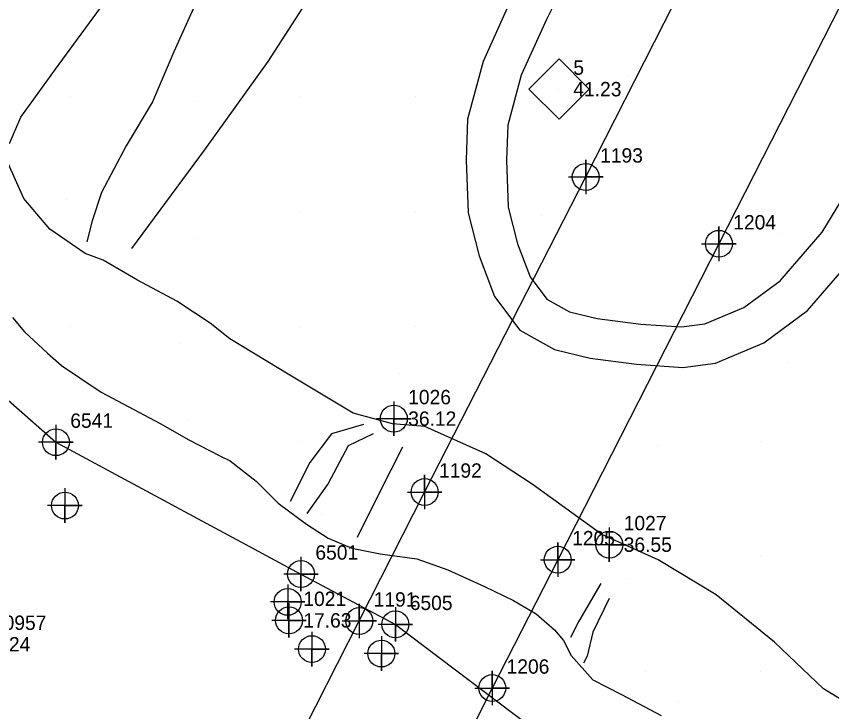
# Model space of a CAD drawing. Extents: x 2062781 to 2066835, y 358981 to 366501.
# Drawn here: x 2064361.2 to 2064503, y 362163.3 to 362284.3 of the extents above; entities that cross this region are included whole.
import ezdxf

# ---------------------------------------------------------------- set-up
doc = ezdxf.new("R2010")
doc.units = 0
for name, color, linetype in [('COGO Default Point Elevation', 7, 'Continuous'), ('COGO Default Point Number', 7, 'Continuous'), ('CTL Supplemental Horizontal and Vertical CELL', 7, 'Continuous'), ('CTL Supplemental Horizontal and Vertical Cogo Elevation', 7, 'Continuous'), ('CTL Supplemental Horizontal and Vertical Cogo Number', 7, 'Continuous'), ('Exist DTM Breakline Underwater', 7, 'Continuous'), ('Exist DTM Breakline Underwater Cogo Elevation', 7, 'Continuous'), ('Exist DTM Breakline Underwater Cogo Number', 7, 'Continuous'), ('Exist DTM Breakline Underwater Cogo Point CELL', 7, 'Continuous'), ('Exist DTM Regular Point CELL', 7, 'Continuous'), ('Exist DTM Regular Point Underwater CELL', 7, 'Continuous'), ('Exist DTM Ridgeline Cogo Elevation', 7, 'Continuous'), ('Exist DTM Ridgeline Cogo Number', 7, 'Continuous'), ('Exist Structure Major Deck Tunnel Box Culvert', 7, 'Continuous'), ('Exist Structure Major Deck Tunnel Box Culvert Cogo Number', 7, 'Continuous'), ('Exist Structure Major Deck Tunnel Box Culvert Cogo Point CELL', 7, 'Continuous'), ('PH Exist DTM Breakline', 7, 'Continuous'), ('PH Exist DTM Point', 7, 'Continuous')]:
    doc.layers.add(name, color=color, linetype=linetype)

msp = doc.modelspace()

# ---------------------------------------------------------------- linework, layer by layer
at = {"layer": 'CTL Supplemental Horizontal and Vertical CELL'}
msp.add_line((2064455.54, 362271.6), (2064455.54, 362271.6), dxfattribs=at)
msp.add_lwpolyline([(2064450.33, 362271.61), (2064455.57, 362276.86), (2064460.82, 362271.61), (2064455.58, 362266.36)], close=True, dxfattribs=at)
at = {"layer": 'Exist DTM Breakline Underwater'}
msp.add_line((2064368.08, 362210.17), (2064410.69, 362187.23), dxfattribs=at)
for points in [[(2064339.75, 362248.83), (2064351.39, 362224.83), (2064368.08, 362210.17)], [(2064410.69, 362187.23), (2064427.1, 362178.47), (2064455.36, 362157.12), (2064487.72, 362143.73), (2064527.72, 362110.81), (2064562.48, 362081.09), (2064591.81, 362074.54), (2064612.39, 362060.79)]]:
    msp.add_lwpolyline(points, dxfattribs=at)
at = {"layer": 'Exist DTM Breakline Underwater Cogo Point CELL'}
for points in [[(2064368.08, 362213.17), (2064368.08, 362207.17), (2064368.08, 362210.17), (2064371.08, 362210.17), (2064365.08, 362210.17)], [(2064368.08, 362213.17), (2064368.08, 362207.17), (2064368.08, 362210.17), (2064371.08, 362210.17), (2064365.08, 362210.17)], [(2064368.08, 362213.17), (2064368.08, 362207.17), (2064368.08, 362210.17), (2064371.08, 362210.17), (2064365.08, 362210.17)], [(2064410.69, 362190.23), (2064410.69, 362184.23), (2064410.69, 362187.23), (2064413.69, 362187.23), (2064407.69, 362187.23)], [(2064410.69, 362190.23), (2064410.69, 362184.23), (2064410.69, 362187.23), (2064413.69, 362187.23), (2064407.69, 362187.23)], [(2064410.69, 362190.23), (2064410.69, 362184.23), (2064410.69, 362187.23), (2064413.69, 362187.23), (2064407.69, 362187.23)], [(2064408.6, 362182.17), (2064408.6, 362176.17), (2064408.6, 362179.17), (2064411.6, 362179.17), (2064405.6, 362179.17)], [(2064427.1, 362181.47), (2064427.1, 362175.47), (2064427.1, 362178.47), (2064430.1, 362178.47), (2064424.1, 362178.47)], [(2064427.1, 362181.47), (2064427.1, 362175.47), (2064427.1, 362178.47), (2064430.1, 362178.47), (2064424.1, 362178.47)], [(2064427.1, 362181.47), (2064427.1, 362175.47), (2064427.1, 362178.47), (2064430.1, 362178.47), (2064424.1, 362178.47)]]:
    msp.add_lwpolyline(points, dxfattribs=at)
for centre in [(2064368.08, 362210.17), (2064368.08, 362210.17), (2064368.08, 362210.17), (2064410.69, 362187.23), (2064410.69, 362187.23), (2064410.69, 362187.23), (2064408.6, 362179.17), (2064427.1, 362178.47), (2064427.1, 362178.47), (2064427.1, 362178.47)]:
    msp.add_circle(centre, 2.34, dxfattribs=at)
at = {"layer": 'Exist DTM Regular Point CELL'}
for points in [[(2064426.83, 362217.26), (2064426.83, 362211.26), (2064426.83, 362214.26), (2064429.83, 362214.26), (2064423.83, 362214.26)], [(2064464.3, 362195.34), (2064464.3, 362189.34), (2064464.3, 362192.34), (2064467.3, 362192.34), (2064461.3, 362192.34)]]:
    msp.add_lwpolyline(points, dxfattribs=at)
for centre in [(2064426.83, 362214.26), (2064464.3, 362192.34)]:
    msp.add_circle(centre, 2.34, dxfattribs=at)
at = {"layer": 'Exist DTM Regular Point Underwater CELL'}
for points in [[(2064369.64, 362202.15), (2064369.64, 362196.15), (2064369.64, 362199.15), (2064372.64, 362199.15), (2064366.64, 362199.15)], [(2064408.38, 362185.39), (2064408.38, 362179.39), (2064408.38, 362182.39), (2064411.38, 362182.39), (2064405.38, 362182.39)], [(2064412.59, 362177.16), (2064412.59, 362171.16), (2064412.59, 362174.16), (2064415.59, 362174.16), (2064409.59, 362174.16)], [(2064424.67, 362176.4), (2064424.67, 362170.4), (2064424.67, 362173.4), (2064427.67, 362173.4), (2064421.67, 362173.4)]]:
    msp.add_lwpolyline(points, dxfattribs=at)
for centre in [(2064369.64, 362199.15), (2064408.38, 362182.39), (2064412.59, 362174.16), (2064424.67, 362173.4)]:
    msp.add_circle(centre, 2.34, dxfattribs=at)
at = {"layer": 'Exist Structure Major Deck Tunnel Box Culvert'}
for points in [[(2064255.42, 361853.85), (2064275.75, 361893.81), (2064296.14, 361933.85), (2064307.58, 361956.23), (2064318.89, 361978.59), (2064330.21, 362000.83), (2064341.53, 362023.17), (2064352.9, 362045.35), (2064364.2, 362067.75), (2064375.5, 362089.93), (2064386.87, 362112.26), (2064398.19, 362134.56), (2064409.53, 362156.83), (2064420.83, 362179.06), (2064432.19, 362201.49), (2064460.2, 362256.32), (2064487.43, 362309.98), (2064514.61, 362363.36), (2064541.87, 362416.97), (2064569.02, 362470.34), (2064596.26, 362523.95)], [(2064619.37, 362512.07), (2064592.26, 362458.71), (2064565.1, 362405.3), (2064537.77, 362351.7), (2064510.65, 362298.32), (2064483.35, 362244.69), (2064455.33, 362189.72), (2064443.94, 362167.39), (2064432.69, 362145.08), (2064421.28, 362122.77), (2064409.98, 362100.46), (2064398.63, 362078.32), (2064387.39, 362056.02), (2064375.97, 362033.72), (2064364.7, 362011.43), (2064353.29, 361989.06), (2064342.01, 361966.81), (2064330.66, 361944.55), (2064319.35, 361922.18), (2064299.02, 361882.17), (2064278.57, 361842.05)]]:
    msp.add_lwpolyline(points, dxfattribs=at)
at = {"layer": 'Exist Structure Major Deck Tunnel Box Culvert Cogo Point CELL'}
for points in [[(2064457.2, 362256.32), (2064463.2, 362256.32), (2064460.2, 362256.32), (2064460.2, 362259.32), (2064460.2, 362253.32)], [(2064457.2, 362256.32), (2064463.2, 362256.32), (2064460.2, 362256.32), (2064460.2, 362259.32), (2064460.2, 362253.32)], [(2064457.2, 362256.32), (2064463.2, 362256.32), (2064460.2, 362256.32), (2064460.2, 362259.32), (2064460.2, 362253.32)], [(2064480.35, 362244.69), (2064486.35, 362244.69), (2064483.35, 362244.69), (2064483.35, 362247.69), (2064483.35, 362241.69)], [(2064480.35, 362244.69), (2064486.35, 362244.69), (2064483.35, 362244.69), (2064483.35, 362247.69), (2064483.35, 362241.69)], [(2064480.35, 362244.69), (2064486.35, 362244.69), (2064483.35, 362244.69), (2064483.35, 362247.69), (2064483.35, 362241.69)], [(2064429.19, 362201.49), (2064435.19, 362201.49), (2064432.19, 362201.49), (2064432.19, 362204.49), (2064432.19, 362198.49)], [(2064429.19, 362201.49), (2064435.19, 362201.49), (2064432.19, 362201.49), (2064432.19, 362204.49), (2064432.19, 362198.49)], [(2064429.19, 362201.49), (2064435.19, 362201.49), (2064432.19, 362201.49), (2064432.19, 362204.49), (2064432.19, 362198.49)], [(2064452.33, 362189.72), (2064458.33, 362189.72), (2064455.33, 362189.72), (2064455.33, 362192.72), (2064455.33, 362186.72)], [(2064452.33, 362189.72), (2064458.33, 362189.72), (2064455.33, 362189.72), (2064455.33, 362192.72), (2064455.33, 362186.72)], [(2064452.33, 362189.72), (2064458.33, 362189.72), (2064455.33, 362189.72), (2064455.33, 362192.72), (2064455.33, 362186.72)], [(2064417.83, 362179.06), (2064423.83, 362179.06), (2064420.83, 362179.06), (2064420.83, 362182.06), (2064420.83, 362176.06)], [(2064417.83, 362179.06), (2064423.83, 362179.06), (2064420.83, 362179.06), (2064420.83, 362182.06), (2064420.83, 362176.06)], [(2064417.83, 362179.06), (2064423.83, 362179.06), (2064420.83, 362179.06), (2064420.83, 362182.06), (2064420.83, 362176.06)], [(2064440.94, 362167.39), (2064446.94, 362167.39), (2064443.94, 362167.39), (2064443.94, 362170.39), (2064443.94, 362164.39)], [(2064440.94, 362167.39), (2064446.94, 362167.39), (2064443.94, 362167.39), (2064443.94, 362170.39), (2064443.94, 362164.39)], [(2064440.94, 362167.39), (2064446.94, 362167.39), (2064443.94, 362167.39), (2064443.94, 362170.39), (2064443.94, 362164.39)]]:
    msp.add_lwpolyline(points, dxfattribs=at)
for centre in [(2064460.2, 362256.32), (2064460.2, 362256.32), (2064460.2, 362256.32), (2064483.35, 362244.69), (2064483.35, 362244.69), (2064483.35, 362244.69), (2064432.19, 362201.49), (2064432.19, 362201.49), (2064432.19, 362201.49), (2064455.33, 362189.72), (2064455.33, 362189.72), (2064455.33, 362189.72), (2064420.83, 362179.06), (2064420.83, 362179.06), (2064420.83, 362179.06), (2064443.94, 362167.39), (2064443.94, 362167.39), (2064443.94, 362167.39)]:
    msp.add_circle(centre, 2.34, dxfattribs=at)
at = {"layer": 'PH Exist DTM Breakline'}
for points in [[(2064381.29, 362243.88), (2064394.11, 362261.22), (2064404.99, 362276.44), (2064411.55, 362286.59), (2064421.3, 362304.39), (2064426.09, 362316.18), (2064435.37, 362335.01), (2064448.84, 362357.44), (2064456.75, 362373.23), (2064465.17, 362390.75), (2064471.34, 362402.76), (2064476.98, 362414.32), (2064480.64, 362422.42), (2064487.69, 362434.9), (2064490.65, 362439.46), (2064494.23, 362441.76), (2064498.58, 362443.24)], [(2064487.25, 362353.73), (2064480.12, 362338.59), (2064475.04, 362327.87), (2064468.83, 362313.95), (2064463.98, 362303.93), (2064458.32, 362293.65), (2064453.35, 362283.72), (2064448.99, 362274.05), (2064446.63, 362265.34), (2064446.42, 362259.27), (2064446.73, 362251.07), (2064448.36, 362244.7), (2064450.52, 362238.95), (2064453.45, 362235.06), (2064457.37, 362232.86), (2064462.21, 362231.7), (2064469.75, 362230.73), (2064476.87, 362230.22), (2064480.93, 362230.75), (2064487.66, 362233.59), (2064493.99, 362238.27), (2064501.33, 362246.73), (2064508.6, 362258.7)], [(2064403.13, 362315.88), (2064398.47, 362303.15), (2064393.64, 362289.32), (2064388.61, 362278.09), (2064384.85, 362269.4), (2064380.27, 362261.76), (2064376.03, 362253.63), (2064374.38, 362248.66), (2064373.44, 362245.03)], [(2064359.99, 362262.14), (2064361.98, 362266.75), (2064368, 362275.1), (2064377.76, 362288.41)], [(2064447.02, 362286.72), (2064442.38, 362276.41), (2064439.66, 362266.39), (2064439.42, 362259.26), (2064439.77, 362250.06), (2064441.67, 362242.59), (2064444.33, 362235.54), (2064448.75, 362229.67), (2064454.79, 362226.28), (2064460.95, 362224.81), (2064469.05, 362223.77), (2064477.08, 362223.19), (2064482.78, 362223.93), (2064491.15, 362227.46), (2064498.77, 362233.1), (2064507.01, 362242.59)], [(2064511.64, 362161.08), (2064501.54, 362167.25), (2064493.01, 362175.38), (2064482.88, 362183.64), (2064472.8, 362189.68), (2064462.97, 362194.09), (2064450.91, 362202.87), (2064442.8, 362208.17), (2064432.2, 362212.88), (2064426.59, 362213.35), (2064419.75, 362215.23), (2064408.76, 362221.85), (2064398.34, 362228.18), (2064394.89, 362230.9), (2064389.13, 362234.71), (2064382.27, 362238.38), (2064376.29, 362241.85), (2064373.16, 362242.98), (2064367.02, 362247.22), (2064362.48, 362252.59), (2064359.86, 362258.55)], [(2064360.53, 362231.85), (2064362.6, 362229.37), (2064366.59, 362225.66), (2064369.04, 362223.54), (2064372.23, 362221.35), (2064375.92, 362218.89), (2064379.76, 362216.85), (2064386.18, 362213.43), (2064391.2, 362210.61), (2064396.71, 362207.76), (2064398.36, 362206.92), (2064402.9, 362203.38), (2064406.73, 362199.58), (2064411.64, 362195.9), (2064415.41, 362193.47), (2064419.51, 362191.75), (2064424.45, 362190.77), (2064430.83, 362189.87), (2064436.21, 362187.95), (2064442.62, 362185.07), (2064447.64, 362182.6), (2064451.6, 362180.31), (2064454.74, 362177.52), (2064456.31, 362175.66), (2064457.64, 362173.04), (2064461.42, 362168.84), (2064466.41, 362166.27), (2064473.32, 362162.6)], [(2064421.53, 362213.25), (2064415.99, 362211.6), (2064412.2, 362206.61), (2064408.81, 362199.86)], [(2064423.24, 362211.65), (2064418.87, 362209.54), (2064415.42, 362202.97), (2064411.69, 362197.74)], [(2064428.33, 362209.33), (2064424.31, 362201.31), (2064420.43, 362193.56)], [(2064462.84, 362185.6), (2064459.01, 362179.02), (2064457.57, 362176.19)], [(2064464.28, 362182.95), (2064461.44, 362177.09), (2064460.43, 362172.93), (2064459.82, 362171.71)]]:
    msp.add_lwpolyline(points, dxfattribs=at)
at = {"layer": 'PH Exist DTM Point'}
for p, q in [((2064467.38, 362273.93), (2064467.38, 362273.93)), ((2064370.65, 362270.27), (2064370.65, 362270.27)), ((2064410.65, 362270.27), (2064410.65, 362270.27)), ((2064430.65, 362270.27), (2064430.65, 362270.27)), ((2064392.73, 362269.47), (2064392.73, 362269.47)), ((2064452.91, 362268.63), (2064452.91, 362268.63)), ((2064369.84, 362252.46), (2064369.84, 362252.46)), ((2064410.65, 362250.27), (2064410.65, 362250.27)), ((2064430.65, 362250.27), (2064430.65, 362250.27)), ((2064452.43, 362249.58), (2064452.43, 362249.58)), ((2064493.9, 362246.51), (2064493.9, 362246.51)), ((2064392.33, 362245.67), (2064392.33, 362245.67)), ((2064370.57, 362230.27), (2064370.57, 362230.27)), ((2064410.61, 362230.21), (2064410.61, 362230.21)), ((2064430.65, 362230.27), (2064430.65, 362230.27)), ((2064389.74, 362227.37), (2064389.74, 362227.37)), ((2064495.37, 362224), (2064495.37, 362224)), ((2064427.84, 362222.19), (2064427.84, 362222.19)), ((2064390.95, 362213.96), (2064390.95, 362213.96)), ((2064410.65, 362210.27), (2064410.65, 362210.27)), ((2064472.65, 362209.62), (2064472.65, 362209.62)), ((2064490.57, 362210.27), (2064490.57, 362210.27)), ((2064414.22, 362197.57), (2064414.22, 362197.57)), ((2064490.65, 362190.27), (2064490.65, 362190.27)), ((2064467.2, 362186.47), (2064467.2, 362186.47)), ((2064470.65, 362170.27), (2064470.65, 362170.27)), ((2064490.63, 362170.24), (2064490.63, 362170.24)), ((2064476.24, 362164.98), (2064476.24, 362164.98))]:
    msp.add_line(p, q, dxfattribs=at)

# ---------------------------------------------------------------- texts
at = {"layer": 'COGO Default Point Elevation'}
msp.add_text('9.24', height=2.5, dxfattribs=at).set_placement((2064357.13, 362173.76))
at = {"layer": 'COGO Default Point Number'}
msp.add_text('10957', height=2.5, dxfattribs=at).set_placement((2064357.13, 362177.51))
at = {"layer": 'CTL Supplemental Horizontal and Vertical Cogo Elevation'}
msp.add_text('41.23', height=2.5, dxfattribs=at).set_placement((2064458.04, 362270.35))
at = {"layer": 'CTL Supplemental Horizontal and Vertical Cogo Number'}
msp.add_text('5', height=2.5, dxfattribs=at).set_placement((2064458.04, 362274.1))
at = {"layer": 'Exist DTM Breakline Underwater Cogo Elevation'}
msp.add_text('17.63', height=2.5, dxfattribs=at).set_placement((2064411.1, 362177.92))
at = {"layer": 'Exist DTM Breakline Underwater Cogo Number'}
for s, p in [('6541', (2064370.58, 362212.67)), ('6541', (2064370.58, 362212.67)), ('6541', (2064370.58, 362212.67)), ('6501', (2064413.19, 362189.73)), ('6501', (2064413.19, 362189.73)), ('6501', (2064413.19, 362189.73)), ('1021', (2064411.1, 362181.67)), ('6505', (2064429.6, 362180.97)), ('6505', (2064429.6, 362180.97)), ('6505', (2064429.6, 362180.97))]:
    msp.add_text(s, height=2.5, dxfattribs=at).set_placement(p)
at = {"layer": 'Exist DTM Ridgeline Cogo Elevation'}
for s, p in [('36.12', (2064429.33, 362213.02)), ('36.55', (2064466.8, 362191.09))]:
    msp.add_text(s, height=2.5, dxfattribs=at).set_placement(p)
at = {"layer": 'Exist DTM Ridgeline Cogo Number'}
for s, p in [('1026', (2064429.33, 362216.77)), ('1027', (2064466.8, 362194.84))]:
    msp.add_text(s, height=2.5, dxfattribs=at).set_placement(p)
at = {"layer": 'Exist Structure Major Deck Tunnel Box Culvert Cogo Number'}
for s, p in [('1193', (2064462.7, 362258.82)), ('1193', (2064462.7, 362258.82)), ('1193', (2064462.7, 362258.82)), ('1204', (2064485.85, 362247.19)), ('1204', (2064485.85, 362247.19)), ('1204', (2064485.85, 362247.19)), ('1192', (2064434.69, 362203.99)), ('1192', (2064434.69, 362203.99)), ('1192', (2064434.69, 362203.99)), ('1205', (2064457.83, 362192.22)), ('1205', (2064457.83, 362192.22)), ('1205', (2064457.83, 362192.22)), ('1191', (2064423.33, 362181.56)), ('1191', (2064423.33, 362181.56)), ('1191', (2064423.33, 362181.56)), ('1206', (2064446.44, 362169.89)), ('1206', (2064446.44, 362169.89)), ('1206', (2064446.44, 362169.89))]:
    msp.add_text(s, height=2.5, dxfattribs=at).set_placement(p)

doc.saveas('drawing.dxf')
